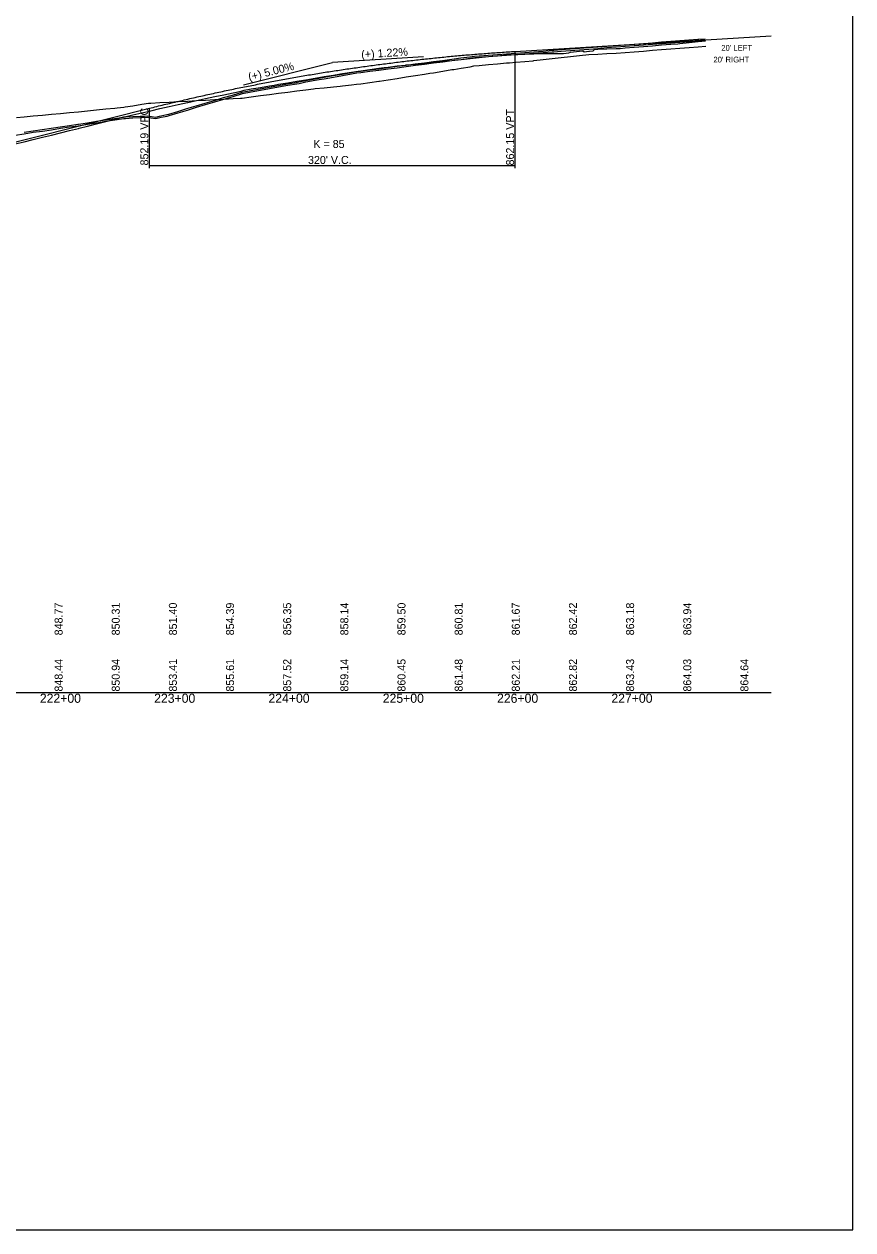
# Model space of a CAD drawing. Extents: x 1475855 to 1480900, y 1104511 to 1111511.
# Drawn here: x 1479329 to 1480054, y 1105041 to 1106096 of the extents above; entities that cross this region are included whole.
import ezdxf

# ---------------------------------------------------------------- set-up
doc = ezdxf.new("R2010")
doc.units = 0
for name, color, linetype in [('RD_DDB_GradeTX', 7, 'Continuous'), ('RD_DDB_Profile_EX', 7, 'Continuous'), ('RD_DDB_Profile_PR', 7, 'Continuous'), ('RD_DDB_StaTX', 7, 'Continuous'), ('RD_DDB_StripGrade', 7, 'Continuous'), ('RD_DDB_VCLbl', 7, 'Continuous'), ('RD_GPK_Profile_Cell', 7, 'Continuous'), ('RD_Sketch2', 7, 'Continuous'), ('RD_Sketch3', 7, 'Continuous'), ('RD_Sketch7', 7, 'Continuous'), ('RD_Sketch8', 7, 'Continuous')]:
    doc.layers.add(name, color=color, linetype=linetype)

msp = doc.modelspace()

# ---------------------------------------------------------------- linework, layer by layer
at = {"layer": 'RD_DDB_GradeTX'}
for p in [(1479520.9, 1106042.8), (1479678.3, 1106067.1)]:
    msp.add_line(p, (1479598.5, 1106062.2), dxfattribs=at)
at = {"layer": 'RD_DDB_Profile_EX'}
msp.add_lwpolyline([(1479321.1, 1105998.8), (1479329, 1106000), (1479336.9, 1106001.2), (1479344.8, 1106002.3), (1479352.7, 1106003.5), (1479360.6, 1106004.7), (1479368.6, 1106005.9), (1479376, 1106007), (1479376.5, 1106007), (1479384.4, 1106008.3), (1479392.3, 1106009.5), (1479400.2, 1106010.8), (1479408.1, 1106012), (1479416, 1106013.2), (1479417.6, 1106013.4), (1479423.9, 1106013.8), (1479430.6, 1106014.1), (1479431.9, 1106014.2), (1479436.4, 1106014.4), (1479439.8, 1106013.9), (1479444, 1106013.2), (1479447.7, 1106014.2), (1479448.7, 1106014.4), (1479454.1, 1106015.4), (1479455.7, 1106015.9), (1479463.7, 1106018.3), (1479471.7, 1106020.7), (1479479.7, 1106023.1), (1479487.6, 1106025.5), (1479495.6, 1106027.9), (1479503.6, 1106030.3), (1479511.6, 1106032.6), (1479519.8, 1106035.1), (1479527.4, 1106036.6), (1479535.5, 1106038), (1479543.5, 1106039.5), (1479551.5, 1106040.9), (1479559.5, 1106042.3), (1479567.4, 1106043.7), (1479569.4, 1106044), (1479575.4, 1106045.2), (1479583.4, 1106046.7), (1479587, 1106047.4), (1479591.4, 1106048.1), (1479599.4, 1106049.5), (1479607.3, 1106050.9), (1479615.3, 1106052.3), (1479620, 1106053.1), (1479623.3, 1106053.5), (1479631.3, 1106054.6), (1479639.3, 1106055.6), (1479645.2, 1106056.3), (1479647.2, 1106056.6), (1479655.2, 1106057.7), (1479663.2, 1106058.7), (1479671.2, 1106059.8), (1479679.2, 1106060.8), (1479687.1, 1106061.9), (1479695.1, 1106062.9), (1479703.1, 1106063.9), (1479711.1, 1106065), (1479719.1, 1106066), (1479723.1, 1106066.6), (1479727, 1106066.9), (1479735, 1106067.5), (1479743, 1106068.1), (1479751, 1106068.7), (1479759, 1106069.2), (1479766.9, 1106069.8), (1479774.9, 1106070.4), (1479782.9, 1106071), (1479790.9, 1106071.6), (1479792.4, 1106071.7), (1479798.8, 1106072.2), (1479806.8, 1106072.8), (1479814.8, 1106073.4), (1479822.8, 1106074), (1479830.8, 1106074.6), (1479838.7, 1106075.3), (1479846.7, 1106075.9), (1479854.7, 1106076.5), (1479862.7, 1106077.1), (1479870.7, 1106077.7), (1479878.6, 1106078.3), (1479886.6, 1106078.9), (1479894.6, 1106079.5), (1479902.6, 1106080.1), (1479910.6, 1106080.7), (1479918.5, 1106081.3), (1479919.1, 1106081.4), (1479924.9, 1106081.8)], dxfattribs=at)
at = {"layer": 'RD_DDB_Profile_PR'}
for p, q in [((1479758.5, 1106072), (1479982.4, 1106085.6)), ((1479151, 1105950.3), (1479438.5, 1106022.2))]:
    msp.add_line(p, q, dxfattribs=at)
msp.add_spline([(1479438.5, 1106022.2), (1479444.9, 1106023.8), (1479451.3, 1106025.4), (1479457.7, 1106026.9), (1479464.1, 1106028.4), (1479470.5, 1106029.9), (1479476.9, 1106031.4), (1479483.3, 1106032.8), (1479489.7, 1106034.2), (1479496.1, 1106035.6), (1479502.5, 1106037), (1479508.9, 1106038.4), (1479515.3, 1106039.7), (1479521.7, 1106041), (1479528.1, 1106042.2), (1479534.5, 1106043.5), (1479540.9, 1106044.7), (1479547.3, 1106045.9), (1479553.7, 1106047.1), (1479560.1, 1106048.3), (1479566.5, 1106049.4), (1479572.9, 1106050.5), (1479579.3, 1106051.6), (1479585.7, 1106052.6), (1479592.1, 1106053.7), (1479598.5, 1106054.7), (1479604.9, 1106055.6), (1479611.3, 1106056.6), (1479617.7, 1106057.5), (1479624.1, 1106058.4), (1479630.5, 1106059.3), (1479636.9, 1106060.2), (1479643.3, 1106061), (1479649.7, 1106061.8), (1479656.1, 1106062.6), (1479662.5, 1106063.4), (1479668.9, 1106064.1), (1479675.3, 1106064.9), (1479681.7, 1106065.6), (1479688.1, 1106066.2), (1479694.5, 1106066.9), (1479700.9, 1106067.5), (1479707.3, 1106068.1), (1479713.7, 1106068.7), (1479720.1, 1106069.2), (1479726.5, 1106069.7), (1479732.9, 1106070.2), (1479739.3, 1106070.7), (1479745.7, 1106071.1), (1479752.1, 1106071.6), (1479758.5, 1106072)], degree=3, dxfattribs=at)
at = {"layer": 'RD_DDB_VCLbl'}
for p, q in [((1479758.5, 1105969.7), (1479758.5, 1106072)), ((1479438.5, 1105969.7), (1479438.5, 1106022.2)), ((1479438.5, 1105972.2), (1479758.5, 1105972.2))]:
    msp.add_line(p, q, dxfattribs=at)
at = {"layer": 'RD_GPK_Profile_Cell'}
msp.add_line((1477363.5, 1105511.2), (1479982.4, 1105511.2), dxfattribs=at)
at = {"layer": 'RD_Sketch2'}
msp.add_lwpolyline([(1479321.1, 1105991.1), (1479329, 1105993), (1479336.9, 1105994.9), (1479344.8, 1105996.9), (1479352.7, 1105998.8), (1479360.6, 1106000.7), (1479368.6, 1106002.7), (1479376.5, 1106004.6), (1479377.1, 1106004.8), (1479384.4, 1106006.6), (1479392.3, 1106008.6), (1479400.2, 1106010.6), (1479408.1, 1106012.6), (1479416, 1106014.6), (1479419.3, 1106015.4), (1479423.9, 1106016.5), (1479431.9, 1106018.3), (1479439.8, 1106020.1), (1479447.7, 1106021.9), (1479455.7, 1106023.7), (1479463.7, 1106025.5), (1479471.7, 1106027.3), (1479472, 1106027.4), (1479479.7, 1106029), (1479487.6, 1106030.7), (1479495.6, 1106032.4), (1479503.6, 1106034.1), (1479511.6, 1106035.8), (1479518.8, 1106037.3), (1479519.6, 1106037.5), (1479521.3, 1106038), (1479527.5, 1106039.1), (1479535.5, 1106040.5), (1479543.5, 1106041.8), (1479547.6, 1106042.5), (1479551.5, 1106043.2), (1479559.5, 1106044.5), (1479567.4, 1106045.9), (1479575.4, 1106047.2), (1479583.4, 1106048.6), (1479591.4, 1106049.9), (1479599.4, 1106051.3), (1479605.5, 1106052.3), (1479607.3, 1106052.6), (1479615.3, 1106053.7), (1479621, 1106054.6), (1479623.3, 1106054.9), (1479631.3, 1106056), (1479639.3, 1106057.2), (1479643.9, 1106057.8), (1479647.2, 1106058.2), (1479655.2, 1106059.2), (1479662.4, 1106060), (1479663.2, 1106060.1), (1479671.2, 1106060.9), (1479679.2, 1106061.7), (1479687.1, 1106062.5), (1479695.1, 1106063.3), (1479703.1, 1106064.1), (1479707.1, 1106064.5), (1479711.1, 1106064.9), (1479719.1, 1106065.8), (1479727, 1106066.6), (1479735, 1106067.5), (1479738.3, 1106067.9), (1479743, 1106068.2), (1479751, 1106068.9), (1479752.2, 1106069), (1479759, 1106069.2), (1479760.8, 1106069.3), (1479766.9, 1106069.5), (1479774.9, 1106069.7), (1479782.9, 1106070), (1479783.7, 1106070), (1479790.9, 1106070.1), (1479798.8, 1106070.2), (1479800.7, 1106070.2), (1479805.4, 1106070.8), (1479806.8, 1106071.4), (1479814.8, 1106072.1), (1479817.5, 1106072.4), (1479818.7, 1106071.6), (1479822.8, 1106072.2), (1479823.5, 1106072.3), (1479826.8, 1106072.5), (1479828, 1106073.9), (1479830.8, 1106074), (1479838.7, 1106074.2), (1479846.7, 1106074.5), (1479850.2, 1106074.6), (1479854.7, 1106075), (1479862.7, 1106075.6), (1479870.7, 1106076.3), (1479878.6, 1106076.9), (1479886.6, 1106077.6), (1479894.6, 1106078.2), (1479900.7, 1106078.7), (1479902.6, 1106078.9), (1479910.6, 1106079.8), (1479918.5, 1106080.6), (1479925.1, 1106081.3)], dxfattribs=at)
at = {"layer": 'RD_Sketch3'}
msp.add_lwpolyline([(1479322.1, 1106014.2), (1479329, 1106014.8), (1479336.9, 1106015.5), (1479344.8, 1106016.2), (1479352.7, 1106017), (1479360.6, 1106017.7), (1479368.6, 1106018.5), (1479376.5, 1106019.2), (1479384.4, 1106020), (1479392.3, 1106020.8), (1479400.2, 1106021.6), (1479408.1, 1106022.4), (1479410.2, 1106022.7), (1479416, 1106023.2), (1479417.3, 1106023.4), (1479423.9, 1106024.4), (1479431.9, 1106025.7), (1479437.8, 1106026.7), (1479439.8, 1106026.8), (1479447.7, 1106027.2), (1479455.7, 1106027.7), (1479463.7, 1106028.1), (1479471.7, 1106028.5), (1479479.7, 1106029), (1479487.6, 1106029.4), (1479495.6, 1106029.8), (1479503.6, 1106030.3), (1479511.6, 1106030.7), (1479518.2, 1106031.1), (1479519.6, 1106031.2), (1479527.5, 1106032.3), (1479535.5, 1106033.3), (1479543.5, 1106034.3), (1479551.5, 1106035.3), (1479559.5, 1106036.4), (1479567.4, 1106037.4), (1479575.4, 1106038.4), (1479582.1, 1106039.3), (1479583.4, 1106039.4), (1479591.4, 1106040.2), (1479599.4, 1106041), (1479605.4, 1106041.6), (1479607.3, 1106041.8), (1479615.3, 1106042.7), (1479619.7, 1106043.3), (1479623.3, 1106043.7), (1479631.3, 1106044.8), (1479639.3, 1106045.9), (1479639.8, 1106046), (1479647.2, 1106047.1), (1479655.2, 1106048.3), (1479663.2, 1106049.6), (1479671.2, 1106050.8), (1479679.2, 1106052), (1479683.9, 1106052.8), (1479687.1, 1106053.3), (1479695.1, 1106054.6), (1479703.1, 1106056), (1479704.7, 1106056.2), (1479711.1, 1106057.3), (1479719.1, 1106058.6), (1479722.3, 1106059.2), (1479727, 1106059.6), (1479735, 1106060.4), (1479743, 1106061.1), (1479751, 1106061.9), (1479753.4, 1106062.1), (1479759, 1106062.6), (1479766.9, 1106063.2), (1479774.2, 1106063.8), (1479774.9, 1106063.9), (1479782.9, 1106064.8), (1479790.9, 1106065.7), (1479798.8, 1106066.6), (1479806.8, 1106067.5), (1479814.8, 1106068.4), (1479822.8, 1106069.2), (1479830.8, 1106069.6), (1479838.7, 1106070), (1479846.7, 1106070.4), (1479854.7, 1106071.1), (1479862.7, 1106071.7), (1479870.7, 1106072.3), (1479878.6, 1106072.9), (1479886.6, 1106073.5), (1479894.6, 1106074.1), (1479902.6, 1106074.7), (1479910.6, 1106075.3), (1479918.5, 1106075.9), (1479925.3, 1106076.4)], dxfattribs=at)
at = {"layer": 'RD_Sketch7'}
msp.add_lwpolyline([(1477173.9, 1105041.2), (1480053.9, 1105041.2), (1480053.9, 1106801.2), (1477173.9, 1106801.2)], close=True, dxfattribs=at)
at = {"layer": 'RD_Sketch8'}
msp.add_lwpolyline([(1479328.8, 1106001.2), (1479336.7, 1106002.4), (1479344.6, 1106003.6), (1479352.6, 1106004.8), (1479360.5, 1106005.9), (1479368.4, 1106007.1), (1479375.8, 1106008.2), (1479376.3, 1106008.3), (1479384.2, 1106009.5), (1479392.1, 1106010.8), (1479400, 1106012), (1479407.9, 1106013.2), (1479415.8, 1106014.4), (1479417.5, 1106014.7), (1479423.9, 1106015), (1479430.5, 1106015.4), (1479431.8, 1106015.4), (1479436.5, 1106015.6), (1479444, 1106014.5), (1479447.4, 1106015.4), (1479448.4, 1106015.6), (1479453.8, 1106016.7), (1479455.4, 1106017.1), (1479463.3, 1106019.5), (1479471.3, 1106021.9), (1479479.3, 1106024.3), (1479487.3, 1106026.7), (1479495.3, 1106029.1), (1479503.2, 1106031.5), (1479511.2, 1106033.8), (1479519.5, 1106036.3), (1479527.2, 1106037.8), (1479535.3, 1106039.3), (1479543.3, 1106040.7), (1479551.3, 1106042.1), (1479559.2, 1106043.5), (1479567.2, 1106044.9), (1479569.2, 1106045.2), (1479575.2, 1106046.4), (1479583.2, 1106047.9), (1479586.8, 1106048.6), (1479591.2, 1106049.4), (1479599.1, 1106050.8), (1479607.1, 1106052.1), (1479615.1, 1106053.5), (1479619.8, 1106054.3), (1479623.1, 1106054.8), (1479631.1, 1106055.8), (1479639.1, 1106056.8), (1479645, 1106057.6), (1479647.1, 1106057.8), (1479655.1, 1106058.9), (1479663, 1106059.9), (1479671, 1106061), (1479679, 1106062), (1479687, 1106063.1), (1479695, 1106064.1), (1479702.9, 1106065.2), (1479710.9, 1106066.2), (1479718.9, 1106067.3), (1479723, 1106067.8), (1479726.9, 1106068.1), (1479734.9, 1106068.7), (1479742.9, 1106069.3), (1479750.9, 1106069.9), (1479758.9, 1106070.5), (1479766.8, 1106071.1), (1479774.8, 1106071.7), (1479782.8, 1106072.3), (1479790.8, 1106072.9), (1479792.3, 1106073), (1479798.8, 1106073.5), (1479806.7, 1106074.1), (1479814.7, 1106074.7), (1479822.7, 1106075.3), (1479830.7, 1106075.9), (1479838.7, 1106076.5), (1479846.6, 1106077.1), (1479854.6, 1106077.7), (1479862.6, 1106078.3), (1479870.6, 1106078.9), (1479878.6, 1106079.5), (1479886.5, 1106080.2), (1479894.5, 1106080.8), (1479902.5, 1106081.4), (1479910.5, 1106082), (1479918.4, 1106082.6), (1479919, 1106082.6), (1479924.8, 1106083)], dxfattribs=at)

# ---------------------------------------------------------------- texts
at = {"layer": 'RD_DDB_GradeTX'}
for s, rotation, p in [('(+) 1.22%', 3.4882, (1479624, 1106065.8)), ('(+) 5.00%', 14.0362, (1479525.9, 1106046.1))]:
    msp.add_text(s, height=7, rotation=rotation, dxfattribs=at).set_placement(p)
at = {"layer": 'RD_DDB_StaTX'}
for s, p in [('222+00', (1479342.6, 1105502.2)), ('223+00', (1479442.6, 1105502.2)), ('224+00', (1479542.6, 1105502.2)), ('225+00', (1479642.6, 1105502.2)), ('226+00', (1479742.6, 1105502.2)), ('227+00', (1479842.6, 1105502.2))]:
    msp.add_text(s, height=8, dxfattribs=at).set_placement(p)
at = {"layer": 'RD_DDB_StripGrade'}
for s, p in [('852.19 VPC', (1479437.5, 1105972.2)), ('862.15 VPT', (1479757.5, 1105972.2)), ('848.77', (1479362.5, 1105561.2)), ('850.31', (1479412.5, 1105561.2)), ('851.40', (1479462.5, 1105561.2)), ('854.39', (1479512.5, 1105561.2)), ('856.35', (1479562.5, 1105561.2)), ('858.14', (1479612.5, 1105561.2)), ('859.50', (1479662.5, 1105561.2)), ('860.81', (1479712.5, 1105561.2)), ('861.67', (1479762.5, 1105561.2)), ('862.42', (1479812.5, 1105561.2)), ('863.18', (1479862.5, 1105561.2)), ('863.94', (1479912.5, 1105561.2)), ('848.44', (1479362.5, 1105512)), ('850.94', (1479412.5, 1105512)), ('853.41', (1479462.5, 1105512)), ('855.61', (1479512.5, 1105512)), ('857.52', (1479562.5, 1105512)), ('859.14', (1479612.5, 1105512)), ('860.45', (1479662.5, 1105512)), ('861.48', (1479712.5, 1105512)), ('862.21', (1479762.5, 1105512)), ('862.82', (1479812.5, 1105512)), ('863.43', (1479862.5, 1105512)), ('864.03', (1479912.5, 1105512)), ('864.64', (1479962.5, 1105512))]:
    msp.add_text(s, height=7, rotation=90, dxfattribs=at).set_placement(p)
at = {"layer": 'RD_DDB_VCLbl'}
for s, p in [('K = 85', (1479581.9, 1105987.5)), ("320' V.C.", (1479577.2, 1105973.5))]:
    msp.add_text(s, height=7, dxfattribs=at).set_placement(p)
at = {"layer": 'RD_Sketch2'}
msp.add_text("20' LEFT", height=5, dxfattribs=at).set_placement((1479938.8, 1106072.6))
at = {"layer": 'RD_Sketch3'}
msp.add_text("20' RIGHT", height=5, dxfattribs=at).set_placement((1479931.9, 1106062.3))

doc.saveas('drawing.dxf')
